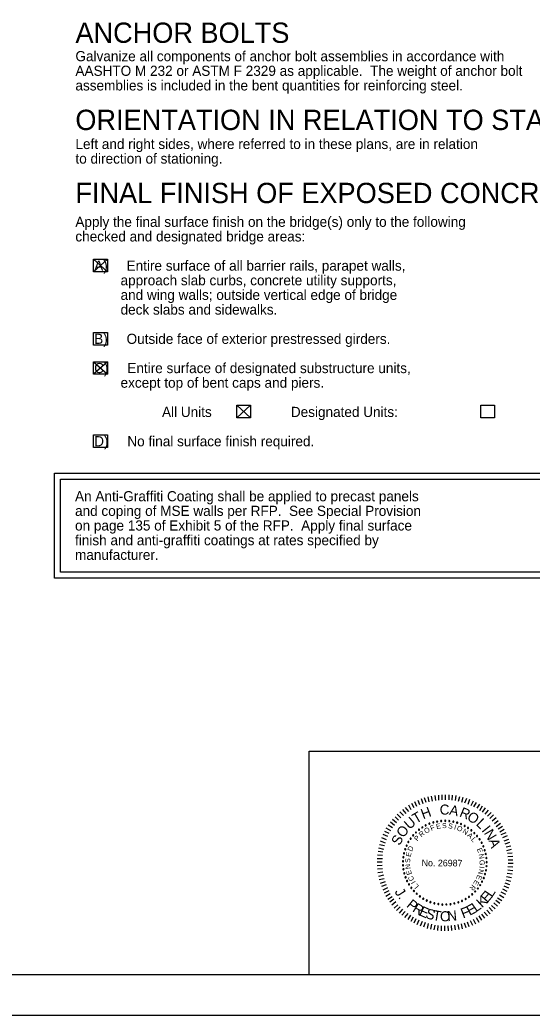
# Model space of a CAD drawing. Extents: x -1.3 to 34.8, y 0.8 to 22.8.
# Drawn here: x 17.75 to 24.06, y 0.82 to 13.07 of the extents above; entities that cross this region are included whole.
import ezdxf

# ---------------------------------------------------------------- set-up
doc = ezdxf.new("R2010")
doc.units = 0
for name, color, linetype in [('BR_BORDER LINES', 7, 'Continuous'), ('BR_TEXT', 7, 'Continuous'), ('Level 31', 7, 'Continuous')]:
    doc.layers.add(name, color=color, linetype=linetype)

msp = doc.modelspace()

# ---------------------------------------------------------------- linework, layer by layer
at = {"layer": 'BR_BORDER LINES'}
for p, q in [((21.311, 4.068), (26.676, 4.068)), ((21.311, 1.318), (21.311, 4.068)), ((0.511, 1.318), (34.177, 1.318))]:
    msp.add_line(p, q, dxfattribs=at)
at = {"layer": 'BR_TEXT'}
for p, q in [((18.654, 10.123), (18.825, 9.968)), ((18.825, 10.123), (18.654, 9.968)), ((18.826, 8.862), (18.655, 8.708)), ((18.655, 8.862), (18.826, 8.708)), ((20.59, 8.327), (20.419, 8.172)), ((20.419, 8.327), (20.59, 8.172)), ((22.641, 3.388), (22.614, 3.444)), ((22.678, 3.405), (22.654, 3.461)), ((22.716, 3.421), (22.695, 3.48)), ((22.756, 3.434), (22.734, 3.492)), ((22.792, 3.444), (22.779, 3.505)), ((22.833, 3.454), (22.819, 3.513)), ((22.873, 3.461), (22.864, 3.522)), ((22.912, 3.465), (22.909, 3.526)), ((22.952, 3.468), (22.952, 3.532)), ((22.994, 3.47), (22.994, 3.532)), ((23.036, 3.467), (23.038, 3.531)), ((23.076, 3.464), (23.081, 3.525)), ((23.115, 3.459), (23.126, 3.52)), ((23.155, 3.451), (23.169, 3.51)), ((23.196, 3.441), (23.212, 3.501)), ((23.233, 3.43), (23.255, 3.487)), ((23.272, 3.417), (23.294, 3.475)), ((23.308, 3.399), (23.336, 3.455)), ((23.344, 3.382), (23.376, 3.437)), ((22.473, 3.275), (22.431, 3.32)), ((22.506, 3.3), (22.466, 3.35)), ((22.54, 3.325), (22.501, 3.376)), ((22.571, 3.346), (22.54, 3.401)), ((22.606, 3.37), (22.576, 3.424)), ((23.382, 3.364), (23.414, 3.417)), ((23.415, 3.339), (23.449, 3.393)), ((23.448, 3.318), (23.485, 3.368)), ((23.481, 3.292), (23.522, 3.341)), ((23.512, 3.266), (23.556, 3.311)), ((22.363, 3.152), (22.314, 3.192)), ((22.389, 3.186), (22.34, 3.225)), ((22.414, 3.217), (22.371, 3.26)), ((22.444, 3.248), (22.399, 3.292)), ((23.54, 3.239), (23.584, 3.282)), ((23.569, 3.208), (23.616, 3.249)), ((23.596, 3.176), (23.642, 3.214)), ((22.3, 3.052), (22.243, 3.08)), ((22.317, 3.087), (22.263, 3.119)), ((22.341, 3.123), (22.288, 3.156)), ((23.619, 3.142), (23.669, 3.181)), ((23.641, 3.113), (23.694, 3.145)), ((23.664, 3.075), (23.717, 3.107)), ((23.681, 3.041), (23.739, 3.068)), ((22.252, 2.937), (22.191, 2.96)), ((22.265, 2.977), (22.207, 2.999)), ((22.282, 3.016), (22.225, 3.041)), ((23.699, 3.004), (23.756, 3.028)), ((23.716, 2.965), (23.773, 2.986)), ((23.729, 2.925), (23.787, 2.947)), ((22.222, 2.823), (22.161, 2.831)), ((22.233, 2.859), (22.17, 2.875)), ((22.24, 2.901), (22.179, 2.916)), ((23.739, 2.889), (23.799, 2.903)), ((23.747, 2.846), (23.808, 2.861)), ((22.215, 2.742), (22.15, 2.743)), ((22.213, 2.701), (22.15, 2.702)), ((22.218, 2.782), (22.156, 2.789)), ((23.756, 2.81), (23.815, 2.818)), ((23.762, 2.769), (23.823, 2.775)), ((23.764, 2.73), (23.824, 2.729)), ((22.214, 2.658), (22.15, 2.657)), ((22.216, 2.62), (22.154, 2.613)), ((22.22, 2.579), (22.159, 2.57)), ((23.761, 2.607), (23.822, 2.599)), ((23.763, 2.646), (23.823, 2.643)), ((23.766, 2.688), (23.827, 2.688)), ((22.23, 2.539), (22.167, 2.526)), ((22.237, 2.497), (22.176, 2.483)), ((22.248, 2.46), (22.186, 2.439)), ((23.736, 2.484), (23.796, 2.469)), ((23.745, 2.526), (23.805, 2.512)), ((23.754, 2.566), (23.813, 2.556)), ((22.26, 2.421), (22.202, 2.4)), ((22.277, 2.384), (22.219, 2.357)), ((22.294, 2.348), (22.237, 2.318)), ((23.675, 2.336), (23.733, 2.306)), ((23.694, 2.372), (23.75, 2.344)), ((23.711, 2.409), (23.768, 2.387)), ((23.725, 2.448), (23.783, 2.426)), ((22.311, 2.311), (22.256, 2.28)), ((22.334, 2.274), (22.28, 2.242)), ((22.356, 2.244), (22.306, 2.208)), ((22.381, 2.211), (22.331, 2.172)), ((23.612, 2.234), (23.661, 2.197)), ((23.634, 2.263), (23.687, 2.231)), ((23.657, 2.3), (23.71, 2.268)), ((22.406, 2.177), (22.362, 2.136)), ((22.435, 2.151), (22.39, 2.106)), ((22.464, 2.121), (22.421, 2.075)), ((22.496, 2.095), (22.455, 2.048)), ((23.471, 2.087), (23.511, 2.039)), ((23.503, 2.112), (23.545, 2.066)), ((23.531, 2.142), (23.574, 2.096)), ((23.56, 2.168), (23.607, 2.126)), ((23.588, 2.201), (23.634, 2.161)), ((22.529, 2.069), (22.489, 2.021)), ((22.56, 2.047), (22.529, 1.995)), ((22.595, 2.024), (22.564, 1.971)), ((22.629, 2.004), (22.602, 1.949)), ((22.666, 1.987), (22.641, 1.931)), ((22.704, 1.969), (22.682, 1.913)), ((23.26, 1.965), (23.281, 1.908)), ((23.297, 1.982), (23.324, 1.926)), ((23.333, 1.999), (23.363, 1.943)), ((23.371, 2.018), (23.402, 1.964)), ((23.404, 2.04), (23.437, 1.987)), ((23.438, 2.061), (23.474, 2.013)), ((22.744, 1.957), (22.721, 1.899)), ((22.78, 1.945), (22.765, 1.886)), ((22.821, 1.938), (22.806, 1.876)), ((22.86, 1.926), (22.85, 1.868)), ((22.9, 1.922), (22.895, 1.86)), ((22.939, 1.919), (22.939, 1.857)), ((22.981, 1.916), (22.981, 1.855)), ((23.023, 1.918), (23.024, 1.856)), ((23.064, 1.92), (23.067, 1.858)), ((23.102, 1.924), (23.112, 1.866)), ((23.143, 1.935), (23.156, 1.873)), ((23.184, 1.941), (23.199, 1.882)), ((23.221, 1.953), (23.242, 1.895))]:
    msp.add_line(p, q, dxfattribs=at)
for points in [[(18.654, 10.123), (18.825, 10.123), (18.825, 9.968), (18.654, 9.968)], [(18.654, 10.123), (18.825, 10.123), (18.825, 9.968), (18.654, 9.968)], [(18.655, 9.223), (18.826, 9.223), (18.826, 9.068), (18.655, 9.068)], [(18.655, 8.862), (18.826, 8.862), (18.826, 8.708), (18.655, 8.708)], [(20.419, 8.327), (20.59, 8.327), (20.59, 8.172), (20.419, 8.172)], [(23.427, 8.327), (23.598, 8.327), (23.598, 8.172), (23.427, 8.172)], [(18.655, 7.961), (18.827, 7.961), (18.827, 7.806), (18.655, 7.806)], [(18.174, 7.489), (24.535, 7.489), (24.535, 6.198), (18.174, 6.198)], [(18.248, 7.415), (24.461, 7.415), (24.461, 6.272), (18.248, 6.272)]]:
    msp.add_lwpolyline(points, close=True, dxfattribs=at)
for centre, start, end in [((22.842, 3.19), 16.1422, 196.1422), ((22.842, 3.19), 196.1422, 16.1422), ((22.89, 3.201), 10.6038, 190.6038), ((22.89, 3.201), 190.6038, 10.6038), ((22.94, 3.208), 5.0653, 185.0653), ((22.94, 3.208), 185.0653, 5.0653), ((22.99, 3.21), 359.5268, 179.5268), ((22.99, 3.21), 179.5268, 359.5268), ((23.039, 3.207), 353.9884, 173.9884), ((23.039, 3.207), 173.9884, 353.9884), ((23.089, 3.199), 348.4499, 168.4499), ((23.089, 3.199), 168.4499, 348.4499), ((23.137, 3.187), 342.9114, 162.9114), ((23.137, 3.187), 162.9114, 342.9114), ((22.628, 3.067), 43.8345, 223.8345), ((22.628, 3.067), 223.8345, 43.8345), ((22.666, 3.1), 38.2961, 218.2961), ((22.666, 3.1), 218.2961, 38.2961), ((22.706, 3.128), 32.7576, 212.7576), ((22.706, 3.128), 212.7576, 32.7576), ((22.749, 3.153), 27.2191, 207.2191), ((22.749, 3.153), 207.2191, 27.2191), ((22.795, 3.174), 21.6807, 201.6807), ((22.795, 3.174), 201.6807, 21.6807), ((23.184, 3.17), 337.373, 157.373), ((23.184, 3.17), 157.373, 337.373), ((23.229, 3.148), 151.8345, 331.8345), ((23.229, 3.148), 331.8345, 151.8345), ((23.271, 3.123), 146.2961, 326.2961), ((23.271, 3.123), 326.2961, 146.2961), ((23.311, 3.093), 140.7576, 320.7576), ((23.311, 3.093), 320.7576, 140.7576), ((23.348, 3.059), 135.2191, 315.2191), ((23.348, 3.059), 315.2191, 135.2191), ((22.536, 2.949), 60.4499, 240.4499), ((22.536, 2.949), 240.4499, 60.4499), ((22.563, 2.991), 54.9114, 234.9114), ((22.563, 2.991), 234.9114, 54.9114), ((22.594, 3.031), 49.373, 229.373), ((22.594, 3.031), 229.373, 49.373), ((23.382, 3.023), 129.6807, 309.6807), ((23.382, 3.023), 309.6807, 129.6807), ((23.412, 2.983), 124.1422, 304.1422), ((23.412, 2.983), 304.1422, 124.1422), ((23.438, 2.94), 118.6038, 298.6038), ((23.438, 2.94), 298.6038, 118.6038), ((22.496, 2.859), 71.5268, 251.5268), ((22.496, 2.859), 251.5268, 71.5268), ((22.514, 2.905), 65.9884, 245.9884), ((22.514, 2.905), 245.9884, 65.9884), ((23.459, 2.895), 113.0653, 293.0653), ((23.459, 2.895), 293.0653, 113.0653), ((23.476, 2.848), 107.5268, 287.5268), ((23.476, 2.848), 287.5268, 107.5268), ((22.469, 2.712), 88.1422, 268.1422), ((22.473, 2.762), 82.6038, 262.6038), ((22.469, 2.712), 268.1422, 88.1422), ((22.473, 2.762), 262.6038, 82.6038), ((22.482, 2.811), 77.0653, 257.0653), ((22.482, 2.811), 257.0653, 77.0653), ((23.489, 2.8), 101.9884, 281.9884), ((23.489, 2.8), 281.9884, 101.9884), ((23.497, 2.751), 96.4499, 276.4499), ((23.5, 2.701), 90.9114, 270.9114), ((23.497, 2.751), 276.4499, 96.4499), ((23.5, 2.701), 270.9114, 90.9114), ((22.47, 2.662), 93.6807, 273.6807), ((22.475, 2.613), 99.2191, 279.2191), ((22.47, 2.662), 273.6807, 93.6807), ((22.475, 2.613), 279.2191, 99.2191), ((23.492, 2.602), 79.8345, 259.8345), ((23.498, 2.652), 85.373, 265.373), ((23.492, 2.602), 259.8345, 79.8345), ((23.498, 2.652), 265.373, 85.373), ((22.485, 2.564), 104.7576, 284.7576), ((22.485, 2.564), 284.7576, 104.7576), ((22.5, 2.516), 110.2961, 290.2961), ((22.5, 2.516), 290.2961, 110.2961), ((22.52, 2.47), 115.8345, 295.8345), ((22.52, 2.47), 295.8345, 115.8345), ((23.444, 2.461), 63.2191, 243.2191), ((23.444, 2.461), 243.2191, 63.2191), ((23.465, 2.506), 68.7576, 248.7576), ((23.465, 2.506), 248.7576, 68.7576), ((23.481, 2.554), 74.2961, 254.2961), ((23.481, 2.554), 254.2961, 74.2961), ((22.544, 2.427), 121.373, 301.373), ((22.544, 2.427), 301.373, 121.373), ((22.571, 2.385), 126.9114, 306.9114), ((22.571, 2.385), 306.9114, 126.9114), ((22.603, 2.347), 132.4499, 312.4499), ((22.603, 2.347), 312.4499, 132.4499), ((23.358, 2.339), 46.6038, 226.6038), ((23.358, 2.339), 226.6038, 46.6038), ((23.391, 2.377), 52.1422, 232.1422), ((23.391, 2.377), 232.1422, 52.1422), ((23.42, 2.418), 57.6807, 237.6807), ((23.42, 2.418), 237.6807, 57.6807), ((22.638, 2.312), 137.9884, 317.9884), ((22.638, 2.312), 317.9884, 137.9884), ((22.677, 2.28), 143.5268, 323.5268), ((22.677, 2.28), 323.5268, 143.5268), ((22.718, 2.252), 149.0653, 329.0653), ((22.718, 2.252), 329.0653, 149.0653), ((22.762, 2.229), 154.6038, 334.6038), ((22.762, 2.229), 334.6038, 154.6038), ((22.808, 2.209), 160.1422, 340.1422), ((22.808, 2.209), 340.1422, 160.1422), ((23.151, 2.206), 18.9114, 198.9114), ((23.151, 2.206), 198.9114, 18.9114), ((23.197, 2.224), 24.4499, 204.4499), ((23.197, 2.224), 204.4499, 24.4499), ((23.241, 2.247), 29.9884, 209.9884), ((23.241, 2.247), 209.9884, 29.9884), ((23.283, 2.274), 35.5268, 215.5268), ((23.283, 2.274), 215.5268, 35.5268), ((23.322, 2.305), 41.0653, 221.0653), ((23.322, 2.305), 221.0653, 41.0653), ((22.856, 2.195), 345.6807, 165.6807), ((22.856, 2.195), 165.6807, 345.6807), ((22.905, 2.185), 351.2191, 171.2191), ((22.905, 2.185), 171.2191, 351.2191), ((22.954, 2.179), 356.7576, 176.7576), ((22.954, 2.179), 176.7576, 356.7576), ((23.004, 2.179), 2.2961, 182.2961), ((23.004, 2.179), 182.2961, 2.2961), ((23.054, 2.183), 7.8345, 187.8345), ((23.054, 2.183), 187.8345, 7.8345), ((23.103, 2.192), 13.373, 193.373), ((23.103, 2.192), 193.373, 13.373)]:
    msp.add_arc(centre, 0.00701, start, end, dxfattribs=at)
at = {"layer": 'Level 31'}
msp.add_lwpolyline([(-1.323, 0.818), (34.677, 0.818), (34.677, 22.818), (-1.323, 22.818)], close=True, dxfattribs=at)

# ---------------------------------------------------------------- texts
at = {"layer": 'BR_TEXT'}
for s, height, p in [('ANCHOR BOLTS', 0.25, (18.431, 12.788)), ('Galvanize all components of anchor bolt assemblies in accordance with ', 0.125, (18.431, 12.562)), ('AASHTO M 232 or ASTM F 2329 as applicable.  The weight of anchor bolt ', 0.125, (18.431, 12.382)), ('assemblies is included in the bent quantities for reinforcing steel.  ', 0.125, (18.431, 12.202)), ('ORIENTATION IN RELATION TO STATIONING', 0.25, (18.43, 11.715)), ('Left and right sides, where referred to in these plans, are in relation ', 0.125, (18.431, 11.481)), ('to direction of stationing.', 0.125, (18.431, 11.301)), ('FINAL FINISH OF EXPOSED CONCRETE SURFACES', 0.25, (18.43, 10.815)), ('Apply the final surface finish on the bridge(s) only to the following ', 0.125, (18.43, 10.523)), ('checked and designated bridge areas:', 0.125, (18.43, 10.343)), ('     A)     Entire surface of all barrier rails, parapet walls, ', 0.125, (18.43, 9.983)), ('            approach slab curbs, concrete utility supports,', 0.125, (18.43, 9.803)), ('            and wing walls; outside vertical edge of bridge', 0.125, (18.43, 9.623)), ('            deck slabs and sidewalks.', 0.125, (18.43, 9.442)), ('     B)     Outside face of exterior prestressed girders.', 0.125, (18.43, 9.082)), ('     C)     Entire surface of designated substructure units,', 0.125, (18.43, 8.722)), ('            except top of bent caps and piers.', 0.125, (18.43, 8.542)), ('                       All Units                     Designated Units:', 0.125, (18.43, 8.182)), ('     D)     No final surface finish required.  ', 0.125, (18.43, 7.821)), ('An Anti-Graffiti Coating shall be applied to precast panels ', 0.125, (18.426, 7.144)), ('and coping of MSE walls per RFP.  See Special Provision', 0.125, (18.426, 6.964)), ('on page 135 of Exhibit 5 of the RFP.  Apply final surface', 0.125, (18.426, 6.784)), ('finish and anti-graffiti coatings at rates specified by ', 0.125, (18.426, 6.603)), ('manufacturer.', 0.125, (18.426, 6.423))]:
    msp.add_text(s, height=height, dxfattribs=at).set_placement(p)
for s, height, rotation, p in [('T', 0.124, 30.4992, (22.629, 3.172)), ('H', 0.124, 20.3637, (22.717, 3.229)), ('C', 0.124, 359.5482, (22.921, 3.287)), ('A', 0.124, 348.1981, (23.033, 3.288)), ('R', 0.124, 337.4344, (23.156, 3.268)), ('O', 0.124, 326.5869, (23.248, 3.232)), ('U', 0.124, 40.8022, (22.548, 3.097)), ('L', 0.124, 315.9488, (23.361, 3.164)), ('O', 0.124, 52.0267, (22.473, 2.993)), ('R', 0.0622, 40.3949, (22.695, 3.006)), ('O', 0.0622, 30.8477, (22.751, 3.05)), ('F', 0.0622, 20.6127, (22.818, 3.086)), ('E', 0.0622, 11.4103, (22.883, 3.108)), ('S', 0.0622, 2.208, (22.951, 3.119)), ('S', 0.0622, 352.6608, (23.022, 3.119)), ('I', 0.0622, 343.1136, (23.093, 3.107)), ('O', 0.0622, 338.4392, (23.126, 3.097)), ('N', 0.0622, 328.2042, (23.196, 3.065)), ('I', 0.124, 308.6613, (23.432, 3.09)), ('N', 0.124, 300.7037, (23.463, 3.06)), ('S', 0.124, 63.2511, (22.428, 2.897)), ('P', 0.0622, 49.9421, (22.646, 2.954)), ('A', 0.0622, 318.657, (23.255, 3.025)), ('L', 0.0622, 309.4546, (23.304, 2.978)), ('A', 0.124, 289.4792, (23.522, 2.967)), ('E', 0.0622, 78.2388, (22.563, 2.762)), ('D', 0.0622, 69.0364, (22.579, 2.828)), ('E', 0.0622, 291.049, (23.378, 2.862)), ('S', 0.0622, 87.786, (22.557, 2.691)), ('No. 26987', 0.0817, 359.5268, (22.698, 2.652)), ('N', 0.0622, 281.8466, (23.4, 2.797)), ('G', 0.0622, 272.2995, (23.412, 2.727)), ('N', 0.0622, 97.3332, (22.563, 2.62)), ('E', 0.0622, 106.5355, (22.58, 2.553)), ('N', 0.0622, 257.7339, (23.407, 2.619)), ('I', 0.0622, 262.4084, (23.412, 2.653)), ('C', 0.0622, 116.4266, (22.61, 2.486)), ('I', 0.0622, 121.1011, (22.628, 2.456)), ('E', 0.0622, 238.9844, (23.361, 2.487)), ('E', 0.0622, 248.1867, (23.389, 2.55)), ('J', 0.124, 302.9559, (22.361, 2.335)), ('L', 0.0622, 129.9595, (22.669, 2.404)), ('R', 0.0622, 229.782, (23.324, 2.43)), ('E', 0.124, 49.3639, (23.507, 2.193)), ('L', 0.124, 56.4247, (23.565, 2.261)), ('.', 0.124, 309.3974, (22.405, 2.267)), ('P', 0.124, 321.1035, (22.504, 2.158)), ('K', 0.124, 42.3031, (23.442, 2.133)), ('R', 0.124, 328.5359, (22.577, 2.1)), ('E', 0.124, 335.9684, (22.657, 2.052)), ('S', 0.124, 343.0292, (22.738, 2.016)), ('T', 0.124, 350.4617, (22.828, 1.99)), ('O', 0.124, 358.1419, (22.923, 1.975)), ('N', 0.124, 5.8221, (23.02, 1.973)), ('F', 0.124, 21.1206, (23.209, 2.007)), ('E', 0.124, 28.1814, (23.291, 2.039)), ('L', 0.124, 35.2422, (23.369, 2.082))]:
    msp.add_text(s, height=height, rotation=rotation, dxfattribs=at).set_placement(p)

doc.saveas('drawing.dxf')
